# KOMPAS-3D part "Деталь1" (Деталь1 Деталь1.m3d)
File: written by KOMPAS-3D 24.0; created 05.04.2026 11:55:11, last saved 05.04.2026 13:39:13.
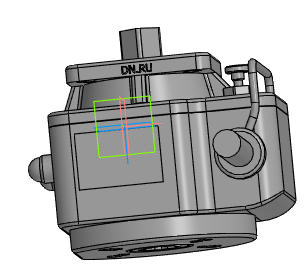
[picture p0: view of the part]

Document properties: Автор: R2D2; Полное имя файла: E:\Работа\Зайцев\Аксессуары для пневмоприводов\Ручной дублер DN.ru\MON4-1200-T54-ISO Ручной дублер DN.ru\исходные материалы\Деталь1 Деталь1.m3d

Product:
- Body: Тело 2  | qty 1
    Масса: 36.924587
- Part/product: Деталь1
    Масса: 35.407781
    additional columns: Типовые

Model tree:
1. Операция без истории:1
2. Эскиз:1  (with: Грань.Операция без истории:1, Ребро.Операция без истории:1)
3. Элемент выдавливания:1  (with: Грань.Операция без истории:1)
     Расстояние 1 = -20.8
4. Скругление:1  (with: Ребро.Элемент выдавливания:1)
     Радиус = 3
